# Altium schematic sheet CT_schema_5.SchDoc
size 479 x 328 mm
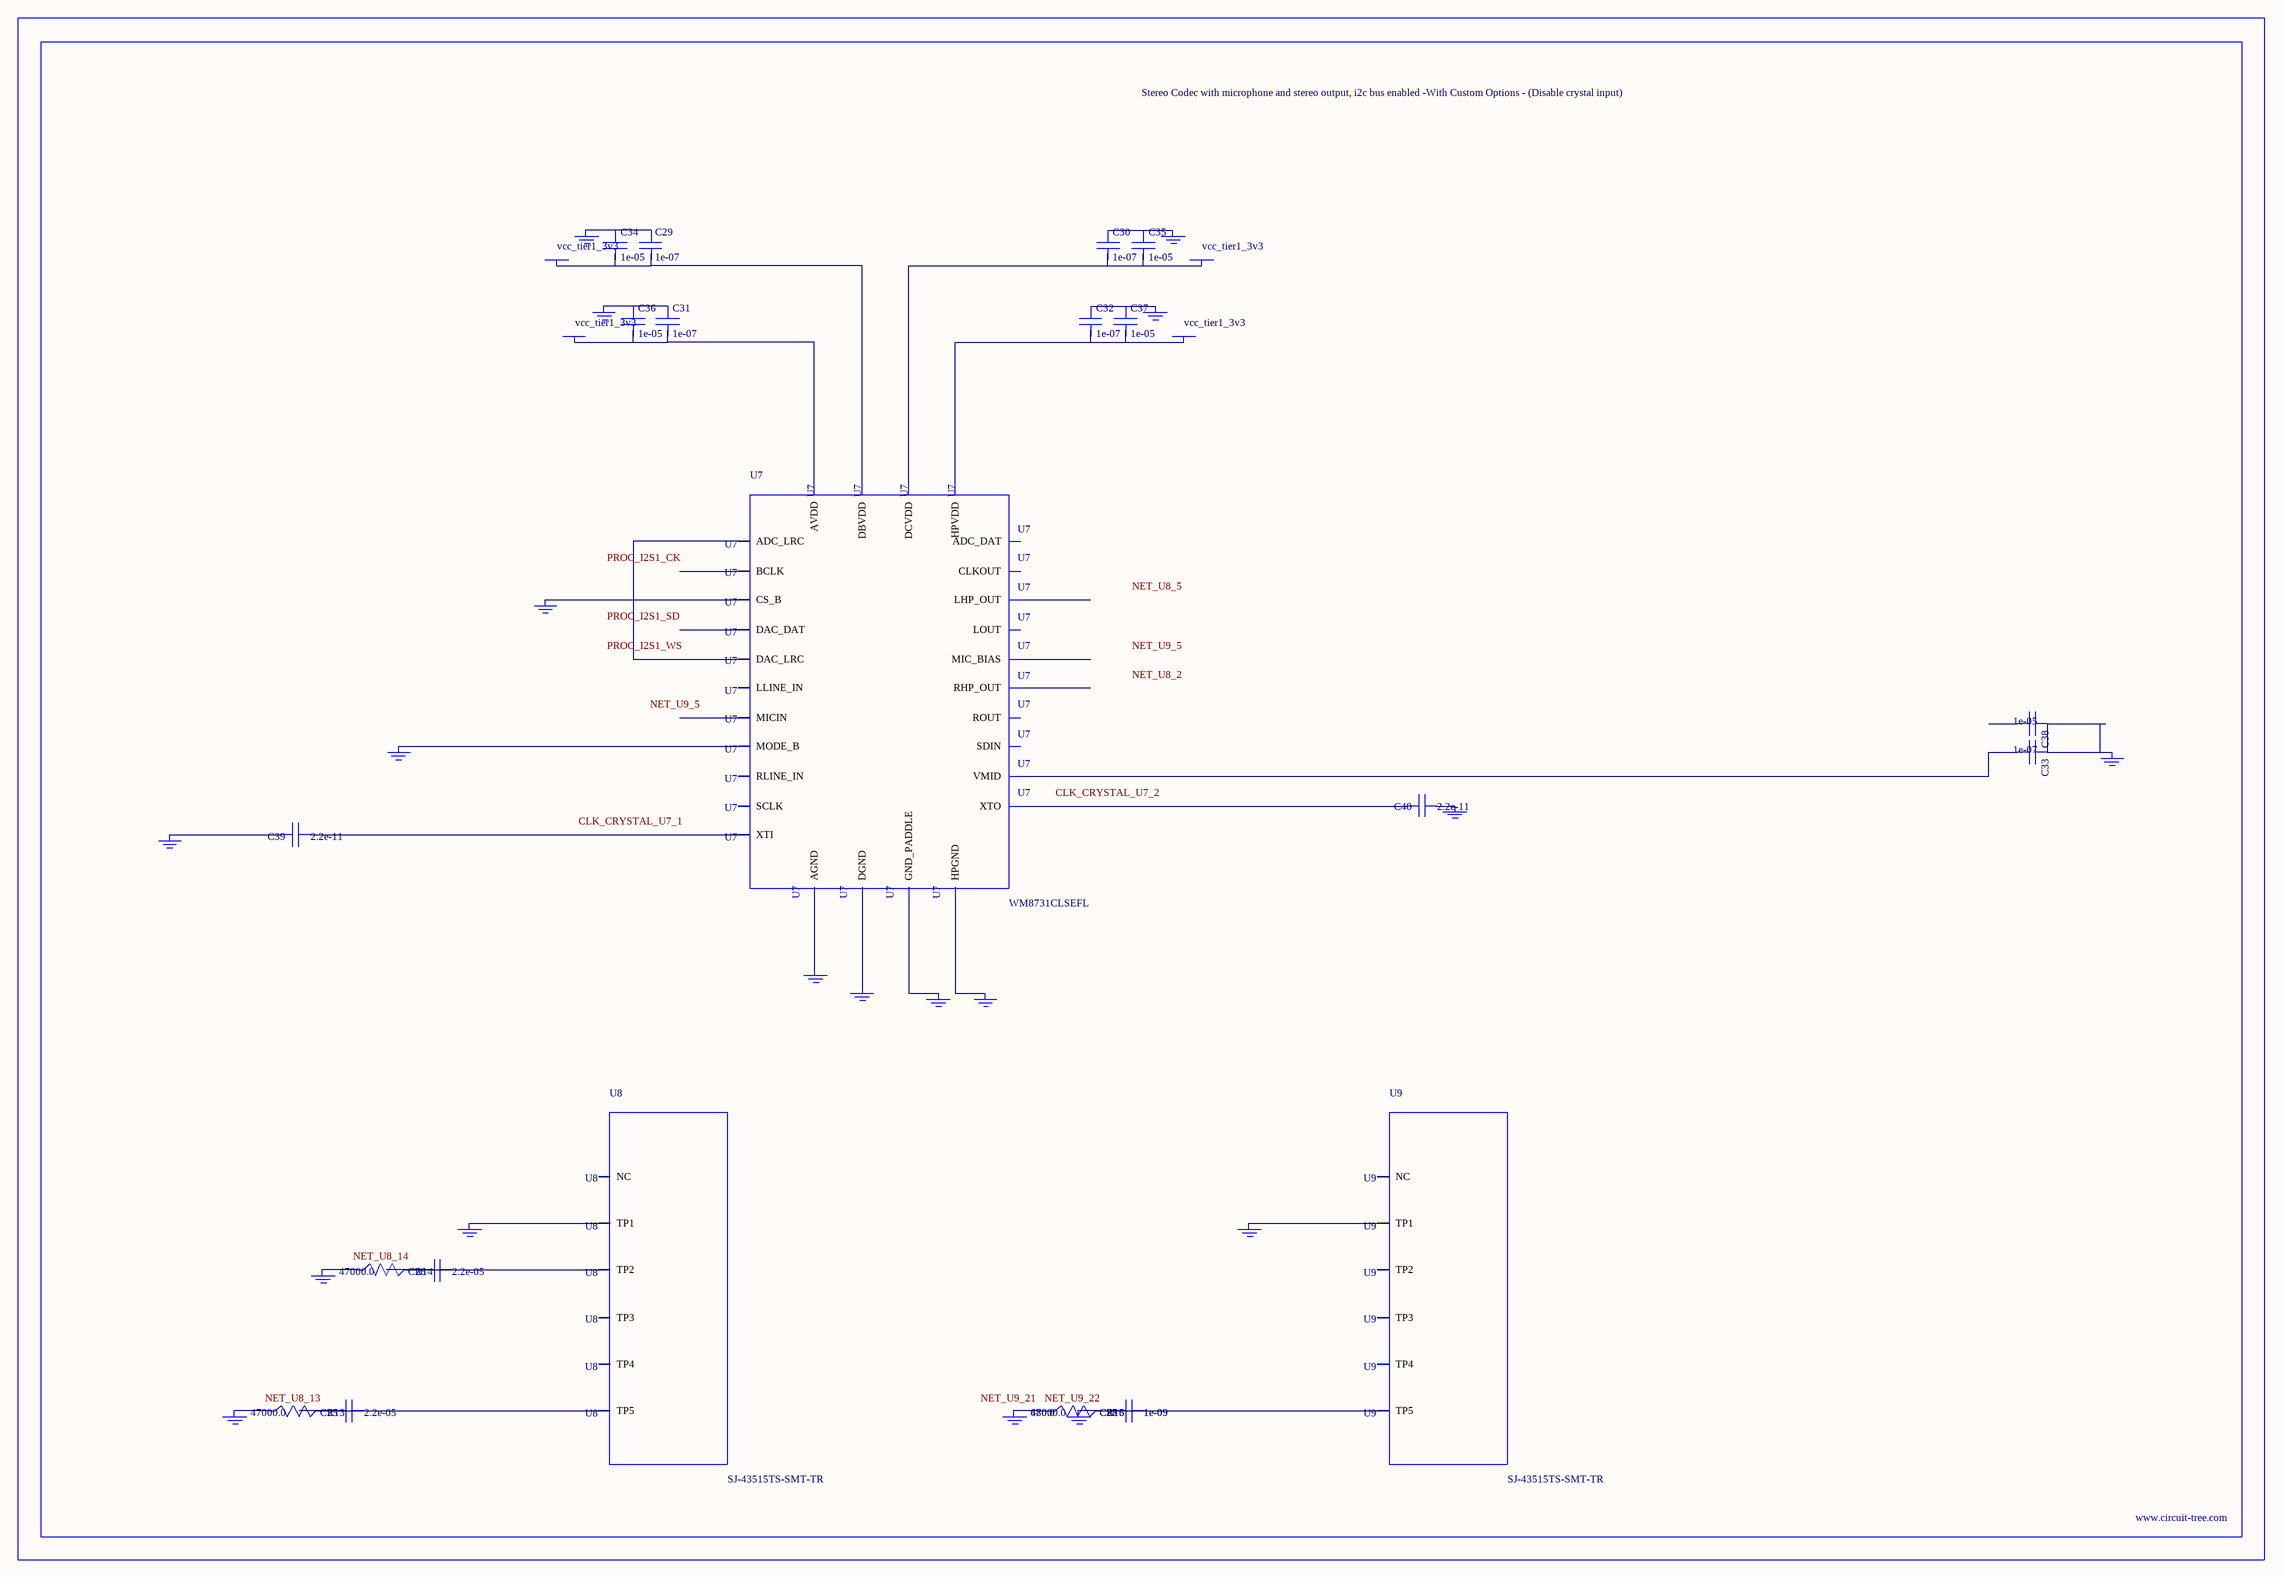
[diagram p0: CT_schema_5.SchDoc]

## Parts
BORDER4  (no value)
C25  2.2e-05  [C1210]
C26  2.2e-05  [C1210]
C27  1e-09  [C0402]
C28  1e-09  [C0402]
C29  1e-07  [C0402]
C30  1e-07  [C0402]
C31  1e-07  [C0402]
C32  1e-07  [C0402]
C33  1e-07  [C0402]
C34  1e-05  [C0805]
C35  1e-05  [C0805]
C36  1e-05  [C0805]
C37  1e-05  [C0805]
C38  1e-05  [C0805]
C39  2.2e-11  [C0402]
C40  2.2e-11  [C0402]
GND_INSTANCE_4_0  (no value)
GND_INSTANCE_4_1  (no value)
GND_INSTANCE_4_2  (no value)
GND_INSTANCE_4_3  (no value)
GND_INSTANCE_4_4  (no value)
GND_INSTANCE_4_5  (no value)
GND_INSTANCE_4_6  (no value)
GND_INSTANCE_4_7  (no value)
GND_INSTANCE_4_8  (no value)
GND_INSTANCE_4_9  (no value)
GND_INSTANCE_4_10  (no value)
GND_INSTANCE_4_11  (no value)
GND_INSTANCE_4_12  (no value)
GND_INSTANCE_4_13  (no value)
GND_INSTANCE_4_14  (no value)
GND_INSTANCE_4_15  (no value)
GND_INSTANCE_4_16  (no value)
GND_INSTANCE_4_17  (no value)
GND_INSTANCE_4_18  (no value)
POWER_INSTANCE_4_0  vcc_tier1_3v3
POWER_INSTANCE_4_1  vcc_tier1_3v3
POWER_INSTANCE_4_2  vcc_tier1_3v3
POWER_INSTANCE_4_3  vcc_tier1_3v3
R13  47000.0  [R0603]
R14  47000.0  [R0603]
R15  47000.0  [R0603]
R16  680.0  [R0603]
U7  WM8731CLSEFL  [QFN-28]
U8  SJ-43515TS-SMT-TR  [SJ-43515TS-SMT-TR]
U9  SJ-43515TS-SMT-TR  [SJ-43515TS-SMT-TR]

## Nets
NetC25_1: C25.1 C25.2 R13.2 U8.5(TP5)
NetC26_1: C26.1 C26.2 R14.2 U8.2(TP2)
NetC27_1: C27.1 C27.2 C28.1 C28.2 GND_INSTANCE_4_18.0(GND) R15.2 R16.2 U9.5(TP5)
NetC29_1: C29.1 C34.1 GND_INSTANCE_4_3.0(GND)
NetC29_2: C29.2 C34.2 POWER_INSTANCE_4_1.0(PWR) U7.5(DBVDD)
NetC30_1: C30.1 C35.1 GND_INSTANCE_4_2.0(GND)
NetC30_2: C30.2 C35.2 POWER_INSTANCE_4_0.0(PWR) U7.3(DCVDD)
NetC31_1: C31.1 C36.1 GND_INSTANCE_4_6.0(GND)
NetC31_2: C31.2 C36.2 POWER_INSTANCE_4_3.0(PWR) U7.18(AVDD)
NetC32_1: C32.1 C37.1 GND_INSTANCE_4_4.0(GND)
NetC32_2: C32.2 C37.2 POWER_INSTANCE_4_2.0(PWR) U7.12(HPVDD)
NetC33_1: C33.1 C38.1 GND_INSTANCE_4_7.0(GND)
NetC33_2: C33.2 U7.20(VMID)
NetC39_1: C39.1 U7.1(XTI)
NetC39_2: C39.2 GND_INSTANCE_4_0.0(GND)
NetC40_1: C40.1 GND_INSTANCE_4_1.0(GND)
NetC40_2: C40.2 U7.2(XTO)
NetGND_INSTANCE_4_5_0: GND_INSTANCE_4_5.0(GND) U7.15(HPGND)
NetGND_INSTANCE_4_8_0: GND_INSTANCE_4_8.0(GND) U7.25(MODE_B)
NetGND_INSTANCE_4_9_0: GND_INSTANCE_4_9.0(GND) U7.26(CS_B)
NetGND_INSTANCE_4_10_0: GND_INSTANCE_4_10.0(GND) U7.29(GND_PADDLE)
NetGND_INSTANCE_4_11_0: GND_INSTANCE_4_11.0(GND) U7.4(DGND)
NetGND_INSTANCE_4_12_0: GND_INSTANCE_4_12.0(GND) U7.19(AGND)
NetGND_INSTANCE_4_13_0: GND_INSTANCE_4_13.0(GND) U8.1(TP1)
NetGND_INSTANCE_4_14_0: GND_INSTANCE_4_14.0(GND) R14.1
NetGND_INSTANCE_4_15_0: GND_INSTANCE_4_15.0(GND) R13.1
NetGND_INSTANCE_4_16_0: GND_INSTANCE_4_16.0(GND) U9.1(TP1)
NetGND_INSTANCE_4_17_0: GND_INSTANCE_4_17.0(GND) R15.1 R16.1
NetU7_9: U7.9(DAC_LRC) U7.11(ADC_LRC)

Not connected (* = marked no-connect by the designer): C38 2; U7 6(CLKOUT) 7(BCLK) 8(DAC_DAT) 10(ADC_DAT) 13(LHP_OUT) 14(RHP_OUT) 16(LOUT) 17(ROUT) 21(MIC_BIAS) 22(MICIN) 23(RLINE_IN) 24(LLINE_IN) 27(SDIN) 28(SCLK); U8 3(TP3) 4(TP4) 6(NC); U9 2(TP2) 3(TP3) 4(TP4) 6(NC)

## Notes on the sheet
- Labels drawn without touching a wire or pin: CLK_CRYSTAL_U7_1, CLK_CRYSTAL_U7_2, NET_U8_2, NET_U8_5, NET_U8_13, NET_U8_14, NET_U9_5, NET_U9_21, NET_U9_22, PROC_I2S1_CK, PROC_I2S1_SD, PROC_I2S1_WS

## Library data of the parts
BORDER4 = BORDER_PAGE4
C25 C26 = C1210C224K5RACTU
C27 C28 = C0402C102K3RAC
C29-C33 = C0402C104K3RACTU
C34-C38 = C0805C106K8RACTU
C39 C40 = C0402C220K3RAC
GND_INSTANCE_4_0-GND_INSTANCE_4_18 = GND
POWER_INSTANCE_4_0-POWER_INSTANCE_4_3 = PWR
R13-R15 = RC0603JR-0747KL
R16 = RC0603JR-07680RL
